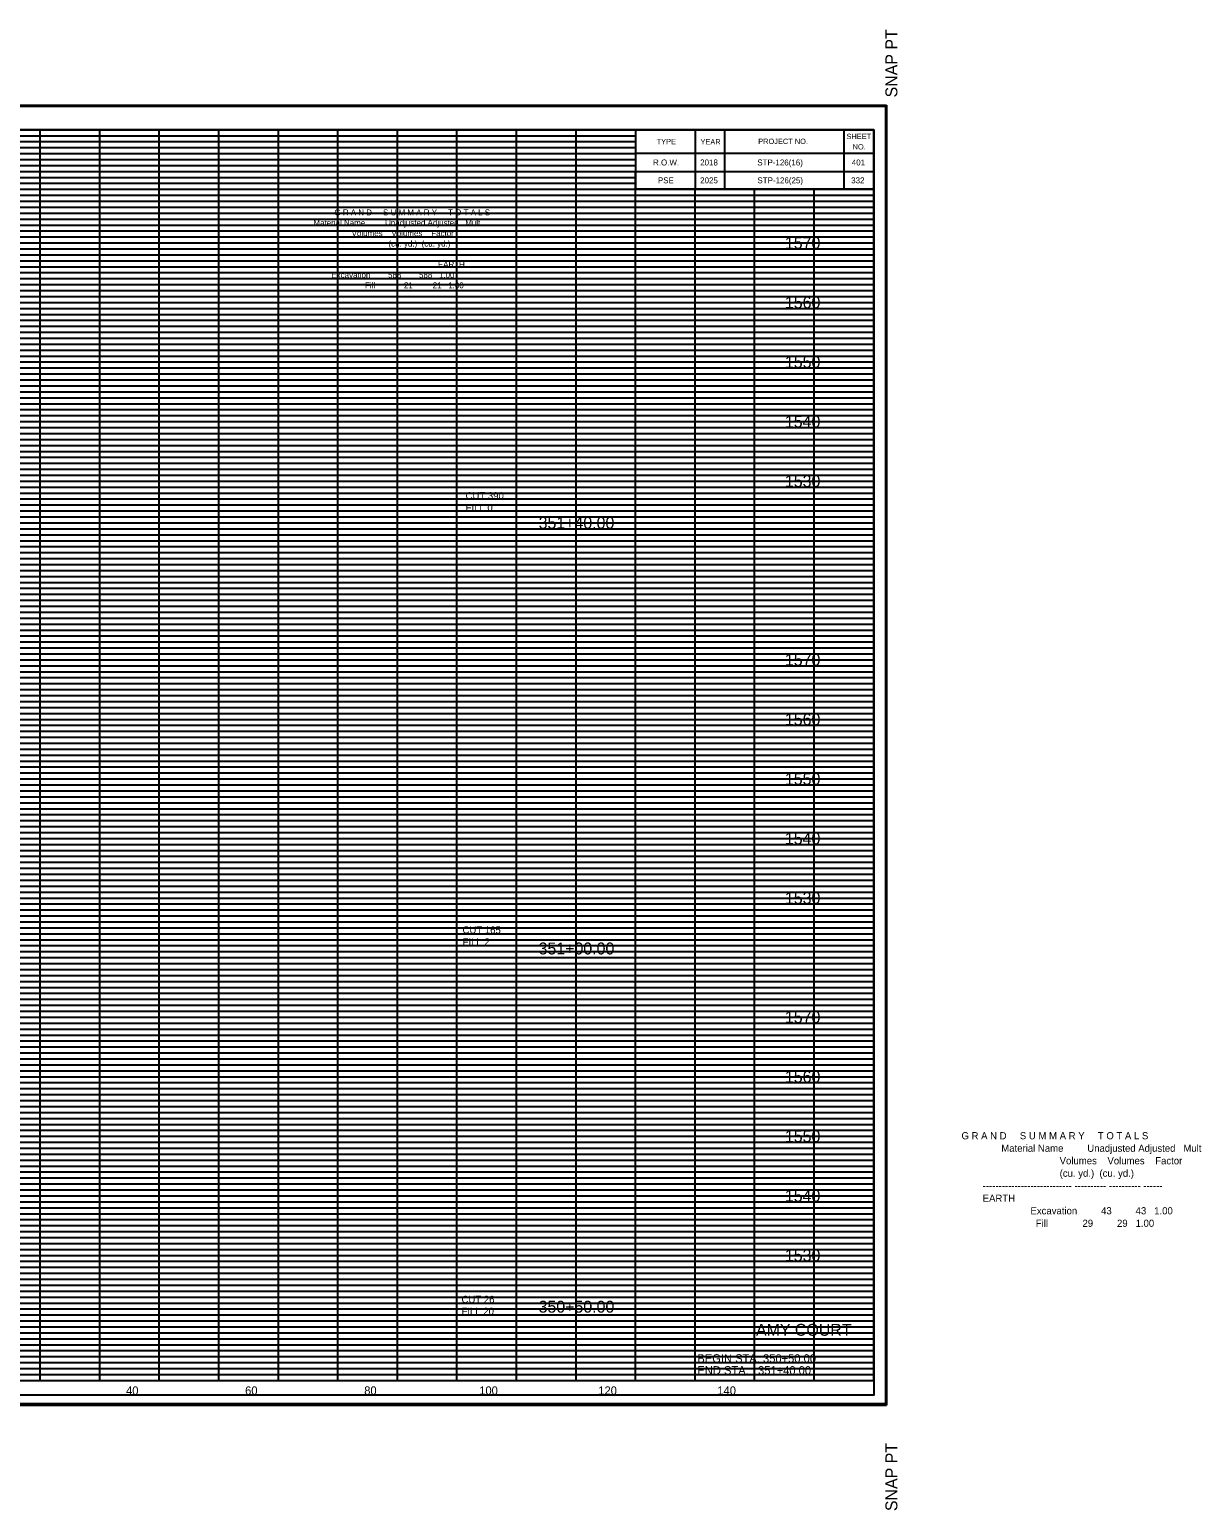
# Model space of a CAD drawing. Extents: x 980 to 1375, y 978 to 1227.
# Drawn here: x 1178.2 to 1375, y 978.2 to 1226.8 of the extents above; entities that cross this region are included whole.
import ezdxf

# ---------------------------------------------------------------- set-up
doc = ezdxf.new("R2010")
doc.units = 0
for name, color, linetype in [('DESIGN - SCRATCH - User 1', 7, 'Continuous'), ('DESIGN - SHEET - Corner Text', 7, 'Continuous'), ('DESIGN - SHEET - Light Grid', 7, 'Continuous'), ('DESIGN - SHEET - Linework', 7, 'Continuous'), ('DESIGN - SHEET - Plot Shape', 7, 'Continuous'), ('DESIGN - TYPICAL - Text', 7, 'Continuous')]:
    doc.layers.add(name, color=color, linetype=linetype)

msp = doc.modelspace()

# ---------------------------------------------------------------- linework, layer by layer
at = {"layer": 'DESIGN - SCRATCH - User 1'}
for p, q in [((1285, 1204.5), (1285, 1204.5)), ((1292.4, 1204.5), (1292.4, 1204.5)), ((1304.9, 1204.5), (1304.9, 1204.5)), ((1317.4, 1204.5), (1317.4, 1204.5)), ((1285, 1201.5), (1285, 1201.5)), ((1292.4, 1201.5), (1292.4, 1201.5)), ((1304.9, 1201.5), (1304.9, 1201.5)), ((1317.4, 1201.5), (1317.4, 1201.5))]:
    msp.add_line(p, q, dxfattribs=at)
at = {"layer": 'DESIGN - SHEET - Light Grid'}
for p, q in [((1160, 1209), (1240, 1209)), ((1240, 1209), (1280, 1209)), ((1160, 1208), (1240, 1208)), ((1160, 1207), (1240, 1207)), ((1160, 1206), (1240, 1206)), ((1240, 1208), (1280, 1208)), ((1240, 1207), (1280, 1207)), ((1240, 1206), (1280, 1206)), ((1160, 1205), (1240, 1205)), ((1160, 1204), (1240, 1204)), ((1240, 1205), (1280, 1205)), ((1240, 1204), (1280, 1204)), ((1160, 1203), (1240, 1203)), ((1160, 1202), (1240, 1202)), ((1160, 1201), (1240, 1201)), ((1240, 1203), (1280, 1203)), ((1240, 1202), (1280, 1202)), ((1240, 1201), (1280, 1201)), ((1160, 1199), (1240, 1199)), ((1240, 1199), (1320, 1199)), ((1160, 1198), (1240, 1198)), ((1160, 1197), (1240, 1197)), ((1160, 1196), (1240, 1196)), ((1240, 1198), (1320, 1198)), ((1240, 1197), (1320, 1197)), ((1240, 1196), (1320, 1196)), ((1160, 1195), (1240, 1195)), ((1160, 1194), (1240, 1194)), ((1240, 1195), (1320, 1195)), ((1240, 1194), (1320, 1194)), ((1160, 1193), (1240, 1193)), ((1160, 1192), (1240, 1192)), ((1160, 1191), (1240, 1191)), ((1240, 1193), (1320, 1193)), ((1240, 1192), (1320, 1192)), ((1240, 1191), (1320, 1191)), ((1160, 1189), (1240, 1189)), ((1240, 1189), (1320, 1189)), ((1160, 1188), (1240, 1188)), ((1160, 1187), (1240, 1187)), ((1160, 1186), (1240, 1186)), ((1240, 1188), (1320, 1188)), ((1240, 1187), (1320, 1187)), ((1240, 1186), (1320, 1186)), ((1160, 1185), (1240, 1185)), ((1160, 1184), (1240, 1184)), ((1240, 1185), (1320, 1185)), ((1240, 1184), (1320, 1184)), ((1160, 1183), (1240, 1183)), ((1160, 1182), (1240, 1182)), ((1160, 1181), (1240, 1181)), ((1240, 1183), (1320, 1183)), ((1240, 1182), (1320, 1182)), ((1240, 1181), (1320, 1181)), ((1160, 1179), (1240, 1179)), ((1240, 1179), (1320, 1179)), ((1160, 1178), (1240, 1178)), ((1160, 1177), (1240, 1177)), ((1240, 1178), (1320, 1178)), ((1240, 1177), (1320, 1177)), ((1160, 1176), (1240, 1176)), ((1160, 1175), (1240, 1175)), ((1160, 1174), (1240, 1174)), ((1240, 1176), (1320, 1176)), ((1240, 1175), (1320, 1175)), ((1240, 1174), (1320, 1174)), ((1160, 1173), (1240, 1173)), ((1160, 1172), (1240, 1172)), ((1240, 1173), (1320, 1173)), ((1240, 1172), (1320, 1172)), ((1160, 1171), (1240, 1171)), ((1160, 1169), (1240, 1169)), ((1240, 1171), (1320, 1171)), ((1240, 1169), (1320, 1169)), ((1160, 1168), (1240, 1168)), ((1160, 1167), (1240, 1167)), ((1240, 1168), (1320, 1168)), ((1240, 1167), (1320, 1167)), ((1160, 1166), (1240, 1166)), ((1160, 1165), (1240, 1165)), ((1160, 1164), (1240, 1164)), ((1240, 1166), (1320, 1166)), ((1240, 1165), (1320, 1165)), ((1240, 1164), (1320, 1164)), ((1160, 1163), (1240, 1163)), ((1160, 1162), (1240, 1162)), ((1240, 1163), (1320, 1163)), ((1240, 1162), (1320, 1162)), ((1160, 1161), (1240, 1161)), ((1160, 1159), (1240, 1159)), ((1240, 1161), (1320, 1161)), ((1240, 1159), (1320, 1159)), ((1160, 1158), (1240, 1158)), ((1160, 1157), (1240, 1157)), ((1240, 1158), (1320, 1158)), ((1240, 1157), (1320, 1157)), ((1160, 1156), (1240, 1156)), ((1160, 1155), (1240, 1155)), ((1160, 1154), (1240, 1154)), ((1240, 1156), (1320, 1156)), ((1240, 1155), (1320, 1155)), ((1240, 1154), (1320, 1154)), ((1160, 1153), (1240, 1153)), ((1160, 1152), (1240, 1152)), ((1240, 1153), (1320, 1153)), ((1240, 1152), (1320, 1152)), ((1160, 1151), (1240, 1151)), ((1160, 1149), (1240, 1149)), ((1240, 1151), (1320, 1151)), ((1240, 1149), (1320, 1149)), ((1160, 1148), (1240, 1148)), ((1160, 1147), (1240, 1147)), ((1240, 1148), (1320, 1148)), ((1240, 1147), (1320, 1147)), ((1160, 1146), (1240, 1146)), ((1160, 1145), (1240, 1145)), ((1160, 1144), (1240, 1144)), ((1240, 1146), (1320, 1146)), ((1240, 1145), (1320, 1145)), ((1240, 1144), (1320, 1144)), ((1160, 1143), (1240, 1143)), ((1160, 1142), (1240, 1142)), ((1240, 1143), (1320, 1143)), ((1240, 1142), (1320, 1142)), ((1160, 1141), (1240, 1141)), ((1160, 1139), (1240, 1139)), ((1240, 1141), (1320, 1141)), ((1240, 1139), (1320, 1139)), ((1160, 1138), (1240, 1138)), ((1160, 1137), (1240, 1137)), ((1240, 1138), (1320, 1138)), ((1240, 1137), (1320, 1137)), ((1160, 1136), (1240, 1136)), ((1160, 1135), (1240, 1135)), ((1160, 1134), (1240, 1134)), ((1240, 1136), (1320, 1136)), ((1240, 1135), (1320, 1135)), ((1240, 1134), (1320, 1134)), ((1160, 1133), (1240, 1133)), ((1160, 1132), (1240, 1132)), ((1240, 1133), (1320, 1133)), ((1240, 1132), (1320, 1132)), ((1160, 1131), (1240, 1131)), ((1160, 1129), (1240, 1129)), ((1240, 1131), (1320, 1131)), ((1240, 1129), (1320, 1129)), ((1160, 1128), (1240, 1128)), ((1160, 1127), (1240, 1127)), ((1240, 1128), (1320, 1128)), ((1240, 1127), (1320, 1127)), ((1160, 1126), (1240, 1126)), ((1160, 1125), (1240, 1125)), ((1160, 1124), (1240, 1124)), ((1240, 1126), (1320, 1126)), ((1240, 1125), (1320, 1125)), ((1240, 1124), (1320, 1124)), ((1160, 1123), (1240, 1123)), ((1160, 1122), (1240, 1122)), ((1240, 1123), (1320, 1123)), ((1240, 1122), (1320, 1122)), ((1160, 1121), (1240, 1121)), ((1160, 1119), (1240, 1119)), ((1240, 1121), (1320, 1121)), ((1240, 1119), (1320, 1119)), ((1160, 1118), (1240, 1118)), ((1160, 1117), (1240, 1117)), ((1240, 1118), (1320, 1118)), ((1240, 1117), (1320, 1117)), ((1160, 1116), (1240, 1116)), ((1160, 1115), (1240, 1115)), ((1160, 1114), (1240, 1114)), ((1240, 1116), (1320, 1116)), ((1240, 1115), (1320, 1115)), ((1240, 1114), (1320, 1114)), ((1160, 1113), (1240, 1113)), ((1160, 1112), (1240, 1112)), ((1240, 1113), (1320, 1113)), ((1240, 1112), (1320, 1112)), ((1160, 1111), (1240, 1111)), ((1160, 1109), (1240, 1109)), ((1240, 1111), (1320, 1111)), ((1240, 1109), (1320, 1109)), ((1160, 1108), (1240, 1108)), ((1160, 1107), (1240, 1107)), ((1240, 1108), (1320, 1108)), ((1240, 1107), (1320, 1107)), ((1160, 1106), (1240, 1106)), ((1160, 1105), (1240, 1105)), ((1160, 1104), (1240, 1104)), ((1240, 1106), (1320, 1106)), ((1240, 1105), (1320, 1105)), ((1240, 1104), (1320, 1104)), ((1160, 1103), (1240, 1103)), ((1160, 1102), (1240, 1102)), ((1240, 1103), (1320, 1103)), ((1240, 1102), (1320, 1102)), ((1160, 1101), (1240, 1101)), ((1160, 1099), (1240, 1099)), ((1240, 1101), (1320, 1101)), ((1240, 1099), (1320, 1099)), ((1160, 1098), (1240, 1098)), ((1160, 1097), (1240, 1097)), ((1240, 1098), (1320, 1098)), ((1240, 1097), (1320, 1097)), ((1160, 1096), (1240, 1096)), ((1160, 1095), (1240, 1095)), ((1160, 1094), (1240, 1094)), ((1240, 1096), (1320, 1096)), ((1240, 1095), (1320, 1095)), ((1240, 1094), (1320, 1094)), ((1160, 1093), (1240, 1093)), ((1160, 1092), (1240, 1092)), ((1240, 1093), (1320, 1093)), ((1240, 1092), (1320, 1092)), ((1160, 1091), (1240, 1091)), ((1160, 1089), (1240, 1089)), ((1240, 1091), (1320, 1091)), ((1240, 1089), (1320, 1089)), ((1160, 1088), (1240, 1088)), ((1160, 1087), (1240, 1087)), ((1240, 1088), (1320, 1088)), ((1240, 1087), (1320, 1087)), ((1160, 1086), (1240, 1086)), ((1160, 1085), (1240, 1085)), ((1240, 1086), (1320, 1086)), ((1240, 1085), (1320, 1085)), ((1160, 1084), (1240, 1084)), ((1160, 1083), (1240, 1083)), ((1160, 1082), (1240, 1082)), ((1240, 1084), (1320, 1084)), ((1240, 1083), (1320, 1083)), ((1240, 1082), (1320, 1082)), ((1160, 1081), (1240, 1081)), ((1240, 1081), (1320, 1081)), ((1160, 1079), (1240, 1079)), ((1160, 1078), (1240, 1078)), ((1160, 1077), (1240, 1077)), ((1240, 1079), (1320, 1079)), ((1240, 1078), (1320, 1078)), ((1240, 1077), (1320, 1077)), ((1160, 1076), (1240, 1076)), ((1160, 1075), (1240, 1075)), ((1240, 1076), (1320, 1076)), ((1240, 1075), (1320, 1075)), ((1160, 1074), (1240, 1074)), ((1160, 1073), (1240, 1073)), ((1160, 1072), (1240, 1072)), ((1240, 1074), (1320, 1074)), ((1240, 1073), (1320, 1073)), ((1240, 1072), (1320, 1072)), ((1160, 1071), (1240, 1071)), ((1240, 1071), (1320, 1071)), ((1160, 1069), (1240, 1069)), ((1160, 1068), (1240, 1068)), ((1160, 1067), (1240, 1067)), ((1240, 1069), (1320, 1069)), ((1240, 1068), (1320, 1068)), ((1240, 1067), (1320, 1067)), ((1160, 1066), (1240, 1066)), ((1160, 1065), (1240, 1065)), ((1240, 1066), (1320, 1066)), ((1240, 1065), (1320, 1065)), ((1160, 1064), (1240, 1064)), ((1160, 1063), (1240, 1063)), ((1160, 1062), (1240, 1062)), ((1240, 1064), (1320, 1064)), ((1240, 1063), (1320, 1063)), ((1240, 1062), (1320, 1062)), ((1160, 1061), (1240, 1061)), ((1240, 1061), (1320, 1061)), ((1160, 1059), (1240, 1059)), ((1160, 1058), (1240, 1058)), ((1160, 1057), (1240, 1057)), ((1240, 1059), (1320, 1059)), ((1240, 1058), (1320, 1058)), ((1240, 1057), (1320, 1057)), ((1160, 1056), (1240, 1056)), ((1160, 1055), (1240, 1055)), ((1240, 1056), (1320, 1056)), ((1240, 1055), (1320, 1055)), ((1160, 1054), (1240, 1054)), ((1160, 1053), (1240, 1053)), ((1160, 1052), (1240, 1052)), ((1240, 1054), (1320, 1054)), ((1240, 1053), (1320, 1053)), ((1240, 1052), (1320, 1052)), ((1160, 1051), (1240, 1051)), ((1240, 1051), (1320, 1051)), ((1160, 1049), (1240, 1049)), ((1160, 1048), (1240, 1048)), ((1160, 1047), (1240, 1047)), ((1240, 1049), (1320, 1049)), ((1240, 1048), (1320, 1048)), ((1240, 1047), (1320, 1047)), ((1160, 1046), (1240, 1046)), ((1160, 1045), (1240, 1045)), ((1240, 1046), (1320, 1046)), ((1240, 1045), (1320, 1045)), ((1160, 1044), (1240, 1044)), ((1160, 1043), (1240, 1043)), ((1160, 1042), (1240, 1042)), ((1240, 1044), (1320, 1044)), ((1240, 1043), (1320, 1043)), ((1240, 1042), (1320, 1042)), ((1160, 1041), (1240, 1041)), ((1240, 1041), (1320, 1041)), ((1160, 1039), (1240, 1039)), ((1160, 1038), (1240, 1038)), ((1160, 1037), (1240, 1037)), ((1240, 1039), (1320, 1039)), ((1240, 1038), (1320, 1038)), ((1240, 1037), (1320, 1037)), ((1160, 1036), (1240, 1036)), ((1160, 1035), (1240, 1035)), ((1240, 1036), (1320, 1036)), ((1240, 1035), (1320, 1035)), ((1160, 1034), (1240, 1034)), ((1160, 1033), (1240, 1033)), ((1160, 1032), (1240, 1032)), ((1240, 1034), (1320, 1034)), ((1240, 1033), (1320, 1033)), ((1240, 1032), (1320, 1032)), ((1160, 1031), (1240, 1031)), ((1240, 1031), (1320, 1031)), ((1160, 1029), (1240, 1029)), ((1160, 1028), (1240, 1028)), ((1160, 1027), (1240, 1027)), ((1240, 1029), (1320, 1029)), ((1240, 1028), (1320, 1028)), ((1240, 1027), (1320, 1027)), ((1160, 1026), (1240, 1026)), ((1160, 1025), (1240, 1025)), ((1240, 1026), (1320, 1026)), ((1240, 1025), (1320, 1025)), ((1160, 1024), (1240, 1024)), ((1160, 1023), (1240, 1023)), ((1160, 1022), (1240, 1022)), ((1240, 1024), (1320, 1024)), ((1240, 1023), (1320, 1023)), ((1240, 1022), (1320, 1022)), ((1160, 1021), (1240, 1021)), ((1240, 1021), (1320, 1021)), ((1160, 1019), (1240, 1019)), ((1160, 1018), (1240, 1018)), ((1160, 1017), (1240, 1017)), ((1240, 1019), (1320, 1019)), ((1240, 1018), (1320, 1018)), ((1240, 1017), (1320, 1017)), ((1160, 1016), (1240, 1016)), ((1160, 1015), (1240, 1015)), ((1240, 1016), (1320, 1016)), ((1240, 1015), (1320, 1015)), ((1160, 1014), (1240, 1014)), ((1160, 1013), (1240, 1013)), ((1160, 1012), (1240, 1012)), ((1240, 1014), (1320, 1014)), ((1240, 1013), (1320, 1013)), ((1240, 1012), (1320, 1012)), ((1160, 1011), (1240, 1011)), ((1240, 1011), (1320, 1011)), ((1160, 1009), (1240, 1009)), ((1160, 1008), (1240, 1008)), ((1160, 1007), (1240, 1007)), ((1240, 1009), (1320, 1009)), ((1240, 1008), (1320, 1008)), ((1240, 1007), (1320, 1007)), ((1160, 1006), (1240, 1006)), ((1160, 1005), (1240, 1005)), ((1240, 1006), (1320, 1006)), ((1240, 1005), (1320, 1005)), ((1160, 1004), (1240, 1004)), ((1160, 1003), (1240, 1003)), ((1160, 1002), (1240, 1002)), ((1240, 1004), (1320, 1004)), ((1240, 1003), (1320, 1003)), ((1240, 1002), (1320, 1002)), ((1160, 1001), (1240, 1001)), ((1240, 1001), (1320, 1001))]:
    msp.add_line(p, q, dxfattribs=at)
at = {"layer": 'DESIGN - SHEET - Linework'}
for p, q in [((981.77, 1214.14), (1322.17, 1214.14)), ((1322.17, 1214.14), (1322.17, 995.86)), ((1180, 1000), (1180, 1210)), ((1190, 1000), (1190, 1210)), ((1200, 1000), (1200, 1210)), ((1210, 1000), (1210, 1210)), ((1220, 1000), (1220, 1210)), ((1230, 1000), (1230, 1210)), ((1240, 1000), (1240, 1210)), ((1250, 1000), (1250, 1210)), ((1260, 1000), (1260, 1210)), ((1270, 1000), (1270, 1210)), ((1000, 1200), (1280, 1200)), ((1280, 1000), (1280, 1200)), ((1290, 1000), (1290, 1200)), ((1300, 1000), (1300, 1200)), ((1310, 1000), (1310, 1200)), ((1000, 1190), (1320, 1190)), ((1000, 1180), (1320, 1180)), ((1000, 1170), (1320, 1170)), ((1000, 1160), (1320, 1160)), ((1000, 1150), (1320, 1150)), ((1000, 1140), (1320, 1140)), ((1000, 1130), (1320, 1130)), ((1000, 1120), (1320, 1120)), ((1000, 1110), (1320, 1110)), ((1000, 1100), (1320, 1100)), ((1000, 1090), (1320, 1090)), ((1000, 1080), (1320, 1080)), ((1000, 1070), (1320, 1070)), ((1000, 1060), (1320, 1060)), ((1000, 1050), (1320, 1050)), ((1000, 1040), (1320, 1040)), ((1000, 1030), (1320, 1030)), ((1000, 1020), (1320, 1020)), ((1000, 1010), (1320, 1010)), ((981.77, 995.86), (1322.17, 995.86))]:
    msp.add_line(p, q, dxfattribs=at)
for points in [[(1000, 1210), (1000, 1000), (1320, 1000), (1320, 1210), (1000, 1210)], [(1280, 1210), (1280, 1200), (1320, 1200), (1320, 1210), (1315, 1210), (1315, 1200), (1295, 1200), (1295, 1210), (1290, 1210), (1290, 1200), (1320, 1200), (1280, 1200), (1280, 1203), (1320, 1203), (1320, 1206), (1280, 1206)]]:
    msp.add_lwpolyline(points, dxfattribs=at)
at = {"layer": 'DESIGN - SHEET - Plot Shape'}
for points in [[(981.97, 1213.94), (1321.97, 1213.94), (1321.97, 996.06), (981.97, 996.06)], [(991.5, 1210), (1320, 1210), (1320, 997.5), (991.5, 997.5)]]:
    msp.add_lwpolyline(points, close=True, dxfattribs=at)

# ---------------------------------------------------------------- texts
at = {"layer": 'DESIGN - SHEET - Corner Text'}
for s, p in [('  SNAP PT', (1323.97, 1213.94)), ('SNAP PT  ', (1323.97, 978.06))]:
    msp.add_text(s, height=2, rotation=90, dxfattribs=at).set_placement(p)
for s, height, p in [('TYPE', 0.9, (1283.54, 1207.56)), ('YEAR', 0.9, (1290.9, 1207.52)), ('PROJECT NO.', 0.9, (1300.6, 1207.6)), ('SHEET', 0.9, (1315.43, 1208.43)), ('NO.', 0.9, (1316.46, 1206.69)), ('R.O.W.', 1, (1282.94, 1204)), ('2018', 1, (1290.85, 1204)), ('STP-126(16)', 1, (1300.45, 1204)), ('401', 1, (1316.31, 1204)), ('PSE', 1, (1283.75, 1201)), ('2025', 1, (1290.85, 1201)), ('STP-126(25)', 1, (1300.47, 1201)), ('332', 1, (1316.22, 1201)), ('AMY COURT', 2, (1300.23, 1007.5)), ('BEGIN STA. 350+50.00', 1.4, (1290.38, 1003)), ('END STA.   351+40.00', 1.4, (1290.38, 1001))]:
    msp.add_text(s, height=height, dxfattribs=at).set_placement(p)
at = {"layer": 'DESIGN - TYPICAL - Text'}
for s, height, p in [('G R A N D     S U M M A R Y     T O T A L S', 1, (1229.41, 1195.62)), ('               Material Name         Unadjusted Adjusted   Mult', 1, (1220.32, 1193.88)), ('                                     Volumes    Volumes    Factor', 1, (1218.56, 1192.12)), ('                                     (cu. yd.)  (cu. yd.)', 1, (1224.75, 1190.38)), ('     1570     ', 2, (1301.37, 1190)), ('        ---------------------------- ---------- ---------- ------', 1, (1222.85, 1188.62)), ('                          Excavation        588        588   1.00', 1, (1219.25, 1185.12)), ('        EARTH', 1, (1243.82, 1186.88)), ('                            Fill             21         21   1.00', 1, (1224.16, 1183.38)), ('     1560     ', 2, (1301.37, 1180)), ('     1550     ', 2, (1301.37, 1170)), ('     1540     ', 2, (1301.37, 1160)), ('     1530     ', 2, (1301.37, 1150)), ('CUT 390', 1.2, (1251.45, 1147.95)), ('FILL 0', 1.2, (1251.45, 1145.95)), ('     351+40.00     ', 2, (1260, 1143)), ('     1570     ', 2, (1301.37, 1120)), ('     1560     ', 2, (1301.37, 1110)), ('     1550     ', 2, (1301.37, 1100)), ('     1540     ', 2, (1301.37, 1090)), ('     1530     ', 2, (1301.37, 1080)), ('CUT 165', 1.2, (1250.94, 1075.04)), ('FILL 2', 1.2, (1250.94, 1073.04)), ('     351+00.00     ', 2, (1260, 1071.53)), ('     1570     ', 2, (1301.37, 1060)), ('     1560     ', 2, (1301.37, 1050)), ('     1550     ', 2, (1301.37, 1040)), ('G R A N D     S U M M A R Y     T O T A L S', 1.2, (1334.74, 1040.49)), ('               Material Name         Unadjusted Adjusted   Mult', 1.2, (1334.74, 1038.39)), ('                                     Volumes    Volumes    Factor', 1.2, (1334.74, 1036.29)), ('                                     (cu. yd.)  (cu. yd.)', 1.2, (1334.74, 1034.19)), ('     1540     ', 2, (1301.37, 1030)), ('        ---------------------------- ---------- ---------- ------', 1.2, (1334.74, 1032.09)), ('        EARTH', 1.2, (1334.74, 1029.99)), ('                          Excavation         43         43   1.00', 1.2, (1334.74, 1027.89)), ('                            Fill             29         29   1.00', 1.2, (1334.74, 1025.79)), ('     1530     ', 2, (1301.37, 1020)), ('CUT 26', 1.2, (1250.77, 1013.01)), ('FILL 20', 1.2, (1250.77, 1011.01)), ('     350+50.00     ', 2, (1260, 1011.38)), ('     40     ', 1.4, (1191.82, 997.6)), ('     60     ', 1.4, (1211.82, 997.6)), ('     80     ', 1.4, (1231.82, 997.6)), ('     100     ', 1.4, (1251.14, 997.6)), ('     120     ', 1.4, (1271.14, 997.6)), ('     140     ', 1.4, (1291.14, 997.6))]:
    msp.add_text(s, height=height, dxfattribs=at).set_placement(p)

doc.saveas('drawing.dxf')
